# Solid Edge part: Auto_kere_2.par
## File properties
Author: KULL
Template: Iso Metric Part.par
Last saved by: KULL
Revision: 50
Application: Solid Edge
Accuracy: 0,990
Face Style: Model Default
Fill Style: Normal
Coef. of Thermal Exp: 0.0
Thermal Conductivity: 0.0
Specific Heat: 0.0
Modulus of Elasticity: 0.0
Poisson's Ratio: 0.0
Yield Stress: 0.0
Ultimate Stress: 0.0
Elongation: 0.0
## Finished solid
Body 1: solid body, 244 faces, 596 edges, 356 vertices.
  Faces by surface: blend 172, cylinder 26, plane 18, offset 12, torus 8, spline 6, swept 2
  Edges by curve: intersection 378, circle 144, ellipse 46, line 28
Body 2: sheet body, 1 face, 4 edges, 4 vertices.
  Faces by surface: spline 1
  Edges by curve: curve on surface 4
Body 3: sheet body, 1 face, 4 edges, 4 vertices.
  Faces by surface: spline 1
  Edges by curve: circle 2, spline 2
Body 4: sheet body, 1 face, 4 edges, 4 vertices.
  Faces by surface: offset 1
  Edges by curve: curve on surface 4
Body 5: sheet body, 1 face, 4 edges, 4 vertices.
  Faces by surface: spline 1
  Edges by curve: curve on surface 4
Body 6: sheet body, 1 face, 4 edges, 4 vertices.
  Faces by surface: spline 1
  Edges by curve: curve on surface 3, circle 1
Body 7: sheet body, 1 face, 4 edges, 4 vertices.
  Faces by surface: offset 1
  Edges by curve: curve on surface 4
Body 8: sheet body, 1 face, 4 edges, 4 vertices.
  Faces by surface: swept 1
  Edges by curve: line 2, spline 2
Body 9: sheet body, 1 face, 4 edges, 4 vertices.
  Faces by surface: swept 1
  Edges by curve: line 2, spline 2
Body 10: sheet body, 1 face, 4 edges, 4 vertices.
  Faces by surface: spline 1
  Edges by curve: curve on surface 4
Body 11: sheet body, 1 face, 4 edges, 4 vertices.
  Faces by surface: cylinder 1
  Edges by curve: circle 2, line 2
Body 12: sheet body, 1 face, 4 edges, 4 vertices.
  Faces by surface: spline 1
  Edges by curve: curve on surface 3, spline 1
Body 13: sheet body, 1 face, 4 edges, 4 vertices.
  Faces by surface: cylinder 1
  Edges by curve: circle 2, line 2
Body 14: sheet body, 1 face, 4 edges, 4 vertices.
  Faces by surface: cylinder 1
  Edges by curve: circle 2, line 2
Body 15: sheet body, 1 face, 4 edges, 4 vertices.
  Faces by surface: cylinder 1
  Edges by curve: circle 2, line 2
Body 16: sheet body, 1 face, 4 edges, 4 vertices.
  Faces by surface: cylinder 1
  Edges by curve: circle 2, line 2
Bounding box of the edges (mm; curved faces can reach further): 648.574 x 418.467 x 392.991, from (-507.184, -209.2334, -140.5972) to (141.3896, 209.2334, 252.3937).
Cylindrical faces by radius (mm): R40 x2, R54 x4, R57 x4, R59 x4, R62 x4, R513 x1, R516 x2, R537 x1, R540 x2, R595 x1, R597 x1, R598 x2, R600 x2, R2661.2303 x1
Toroidal faces (ring radius, tube radius in mm): R44 r10 x4, R44 r13 x4
Planar faces by outward normal: +y 4, -y 4, -z 1, oblique 9
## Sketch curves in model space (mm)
line (-28.0915, 0, 21.6293) -> (-551.6652, 0, 42.7946)
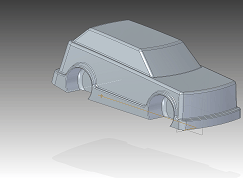
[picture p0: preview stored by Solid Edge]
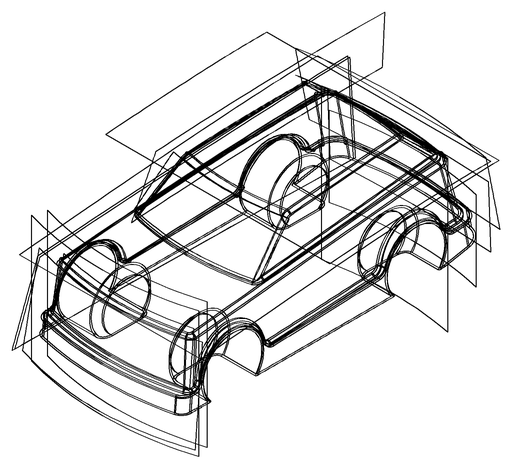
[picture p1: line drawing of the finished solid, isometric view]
